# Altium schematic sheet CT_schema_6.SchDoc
size 281 x 211 mm
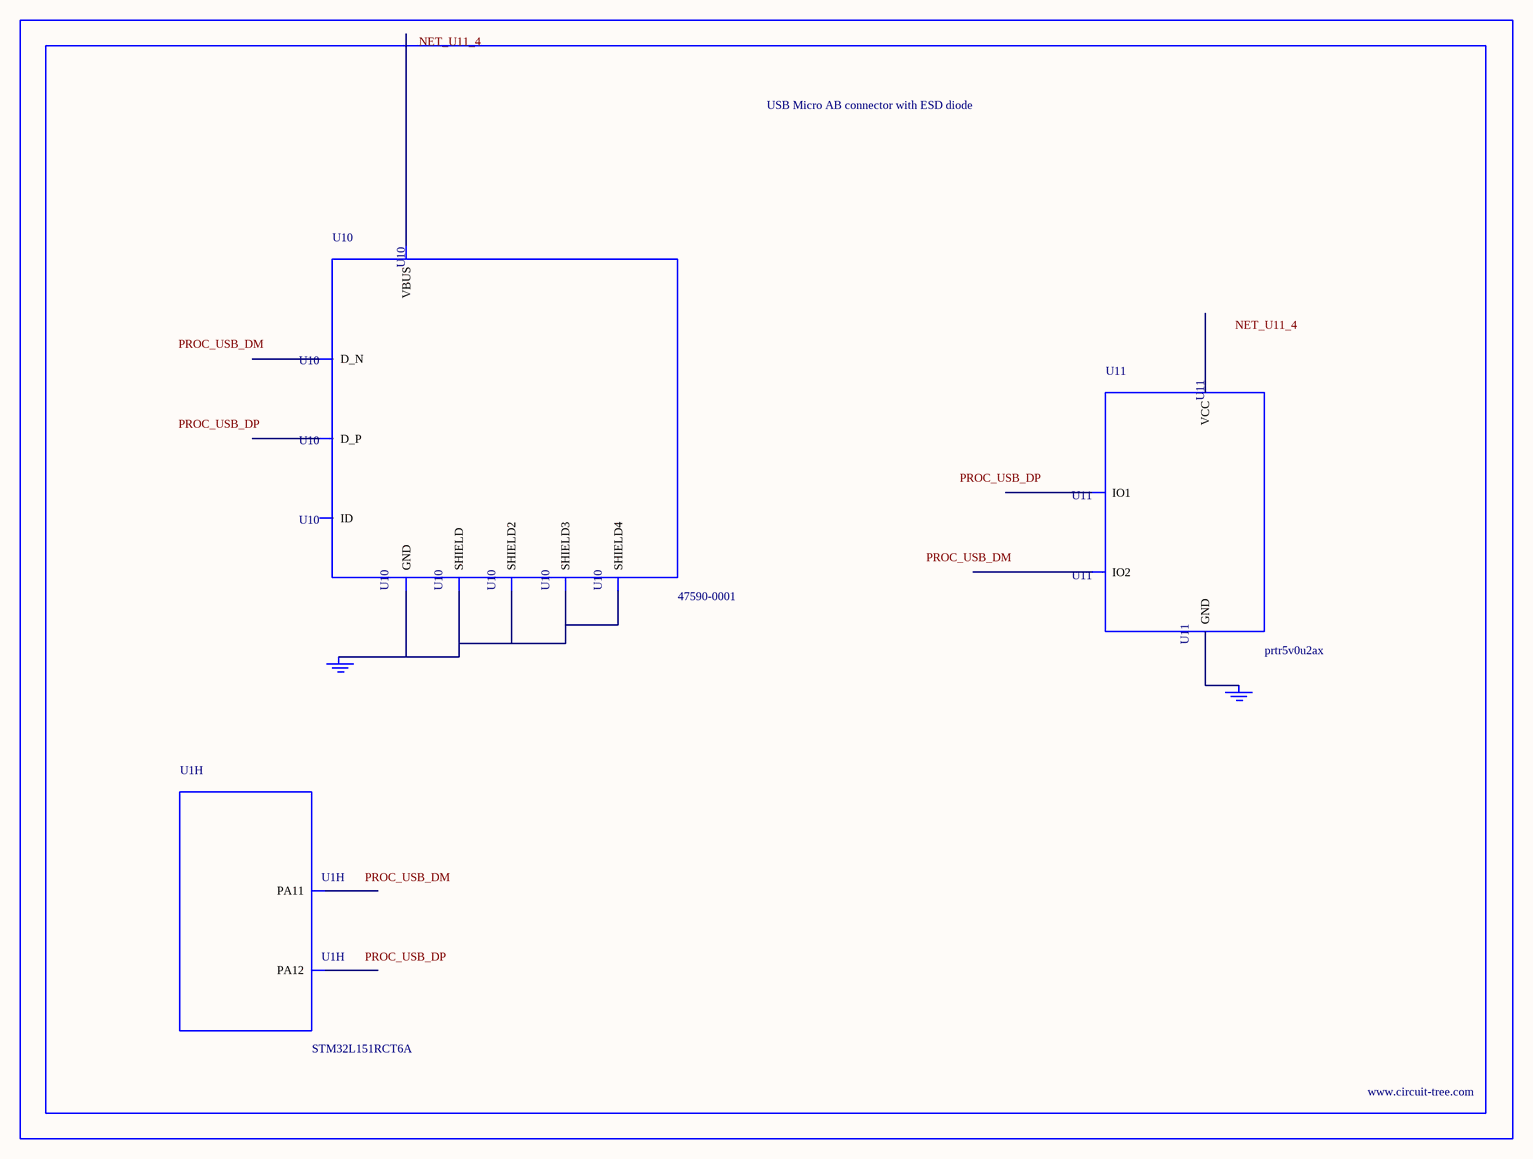
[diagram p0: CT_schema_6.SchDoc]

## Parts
BORDER5  (no value)
GND_INSTANCE_5_0  (no value)
GND_INSTANCE_5_1  (no value)
U1  STM32L151RCT6A  [LQFP64]  (part H of 8)
U10  47590-0001  [MICRO_USB_AB]
U11  prtr5v0u2ax  [SOT143B]

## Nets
NetGND_INSTANCE_5_0_0: GND_INSTANCE_5_0.0(GND) U10.5(GND) U10.6(SHIELD) U10.7(SHIELD2) U10.8(SHIELD3) U10.9(SHIELD4)
NetGND_INSTANCE_5_1_0: GND_INSTANCE_5_1.0(GND) U11.1(GND)

Not connected (* = marked no-connect by the designer): U1 44(PA11) 45(PA12); U10 1(VBUS) 2(D_N) 3(D_P) 4(ID); U11 2(IO1) 3(IO2) 4(VCC)

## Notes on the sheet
- Labels drawn without touching a wire or pin: NET_U11_4, PROC_USB_DM, PROC_USB_DP

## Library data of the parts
BORDER5 = BORDER_PAGE5
GND_INSTANCE_5_0 GND_INSTANCE_5_1 = GND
